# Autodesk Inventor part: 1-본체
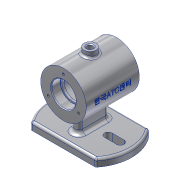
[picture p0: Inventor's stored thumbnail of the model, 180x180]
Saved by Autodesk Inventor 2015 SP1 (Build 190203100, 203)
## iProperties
Created: 2017-12
Part Number: 1-본체
Material: 알루미늄 6061
Document SubType Name: Modeling
Designer: C04
Density: 2.7 g/cm^3
Appearance: 알루미늄 - 평지
Mass: 465.966 g
Surface Area: 486.484 cm^2
Volume: 172.58 cm^3
Author: C04
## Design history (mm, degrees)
sketch "스케치1"
  geometry: L1 (-35, -42.426)-(-35, 42.426); L2 (35, -42.426)-(35, 42.426); L3 (35, 0)-(-35, 0); L4 (0, -24)-(0, -40); L5 (-5, -24)-(-5, -40); L6 (5, -40)-(5, -24); L7 (0, 24)-(0, 40); L8 (5, 24)-(5, 40); L9 (-5, 40)-(-5, 24); A1 r 55 centre (0, 0) between (-35, -42.426) and (35, -42.426); A2 r 55 centre (0, 0) between (35, 42.426) and (-35, 42.426); A3 r 5 centre (0, -24) between (5, -24) and (-5, -24); A4 r 5 centre (0, -40) between (-5, -40) and (5, -40); A5 r 5 centre (0, 24) between (-5, 24) and (5, 24); A6 r 5 centre (0, 40) between (5, 40) and (-5, 40); 4 further points
  constraints: 22 end point, 12 point on circle, 8 tangent, 6 centre point, 5 midpoint, 3 parallel, 3 vertical, 2 coincident
  dimensions: "d1" = 70 distance between parallel lines of L1 L2; "d2" = 5 radius of A6; "d3" = 5 radius of A4; "d4" = 24 vertical distance of L3.end L4.start; "d5" = 16 distance of L4.end L4.start; "d6" = 24 vertical distance of L7.start L3.start; "d7" = 16 distance of L7.end L7.start; "d8" = 55 radius of A1; "d9" = 55 radius of A2
extrude "돌출1" new body sketch "스케치1" distance "d10" = 10; taper "d11" = 0 deg
sketch "스케치3"
  geometry: L1 (0, 42.426)-(0, -42.426) reference; C1 r 30 at (62, 0); 1 further point
  constraints: 1 centre point
  dimensions: "d12" = 62 distance from line of L1 C1.centre; "d13" = 60 diameter of C1
extrude "돌출2" join sketch "스케치3" stored distance "d14" = 70; taper "d15" = 0 deg
sketch "스케치4"
  geometry: L1 (-15, 0)-(15, 0); L2 (-15, -5)-(15, -5); L3 (15, 5)-(-15, 5); A1 r 5 centre (-15, 0) between (-15, 5) and (-15, -5); A2 r 5 centre (15, 0) between (15, -5) and (15, 5); 3 further points
  constraints: 8 end point, 4 point on circle, 4 tangent, 2 centre point, 2 midpoint, 1 horizontal, 1 parallel, 1 vertical alignment
  dimensions: "d16" = 5 radius of A2; "d17" = 30 distance of L3.start L3.end
extrude "돌출3" join sketch "스케치4" stored distance "d18" = 70; taper "d19" = 0 deg; dims "d1" = 70, "d2" = 5, "d3" = 5, "d4" = 24, "d5" = 16, "d6" = 24, "d7" = 16, "d8" = 55, "d9" = 55
node "작업 평면1"
sketch "스케치5"
  geometry: C1 r 8 at (0, 0); 1 further point
  constraints: 1 centre point, 1 coincident
  dimensions: "d21" = 16 diameter of C1
extrude "돌출4" join sketch "스케치5" stored distance "d22" = 70; taper "d23" = 0 deg
sketch "스케치6"
  geometry: L1 (35, 32)-(35, 92) reference; L2 (35, 62)-(-35, 62); L3 (35, 62)-(23, 62); L4 (23, 62)-(23, 78); L5 (23, 78)-(35, 78); L6 (35, 78)-(35, 62); L7 (23, 62)-(20, 62); L8 (20, 62)-(20, 76); L9 (20, 76)-(23, 76); L10 (23, 76)-(23, 62); L11 (20, 62)-(-20, 62); L12 (-20, 62)-(-20, 87); L13 (-20, 87)-(20, 87); L14 (20, 87)-(20, 62); L15 (-20, 62)-(-23, 62); L16 (-23, 62)-(-23, 76); L17 (-23, 76)-(-20, 76); L18 (-20, 76)-(-20, 62); L19 (-23, 62)-(-35, 62); L20 (-35, 92)-(-35, 32) reference; L21 (-23, 62)-(-35, 62); L22 (-35, 62)-(-35, 78); L23 (-35, 78)-(-23, 78); L24 (-23, 78)-(-23, 62); 1 further point
  constraints: 44 end point, 10 parallel, 7 horizontal, 5 perpendicular, 1 midpoint, 1 point on line
  dimensions: "d24" = 32 diameter of L5 L2; "d26" = 70 distance of L2.start L2.end; "d27" = 28 diameter of L9 L2; "d28" = 28 diameter of L17 L2; "d29" = 12 distance of L4.end L5.end; "d31" = 40 distance of L12.end L13.end; "d32" = 50 diameter of L13 L11; "d33" = 3 distance of L8.end L9.end; "d34" = 12 distance of L22.end L23.end; "d35" = 32 diameter of L23 L2
revolve "회전1" sketch "스케치6" stored, may be unused: angle "d36" = 90 deg
sketch "스케치7"
  geometry: 1 further point
hole "구멍1" sketch "스케치7" at (0, 0) diameter "d37" = 8; stored, may be unused: countersink angle "d41" = 90 deg, drill point angle "d43" = 0 deg; dims "d38" = 6, "d39" = 4, "d40" = 2, "d42" = 8
fillet "모깎기1" dims "d44" = 5
fillet "모깎기2" dims "d45" = 3
fillet "모깎기3" dims "d46" = 3
fillet "모깎기4" dims "d47" = 5
chamfer "모따기1" distance "d48" = 1; stored, may be unused: second distance "d49" = 2, angle "d50" = 45 deg
fillet "모깎기5" dims "d51" = 3
fillet "모깎기6" dims "d52" = 0.3
node "작업 평면3"
sketch "스케치9"
  geometry: L1 (-35, 92)-(-35, 32) reference; L2 (-35, 62)-(35, 62); L3 (35, 45)-(35, 79) reference; 2 further points
  constraints: 2 end point, 2 midpoint, 1 other
  dimensions: "d56" = 30 vertical distance of L1.start point (0, 62); "d57" = 35 horizontal distance of L1.start point (0, 62)
feature "엠보싱1" sketch "스케치9" dims "d58" = 0.5, "d59" = 0
sketch "스케치10" dims "d60" = 46
  geometry: 3 further points
  constraints: 1 vertical alignment, 2 other
hole "구멍2" sketch "스케치10" at (0, 23) diameter "d61" = 3.242; stored, may be unused: countersink angle "d65" = 90 deg, drill point angle "d67" = 118 deg; dims "d62" = 8, "d63" = 4, "d64" = 2, "d66" = 10
fillet "모깎기7" dims "d71" = 3
node "솔리드1"
pattern_circular "원형 패턴1" dims angle "d69" = 360 deg
mirror "대칭1"
other parameters: "d20" = 99
